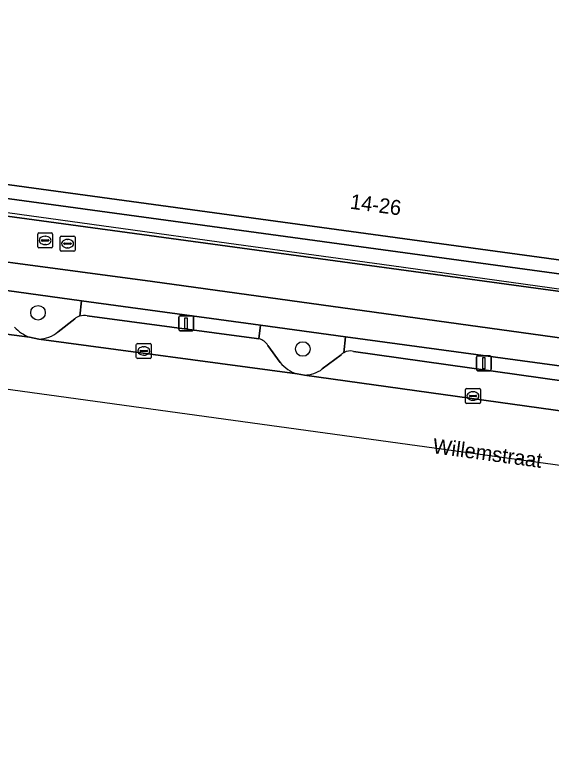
# Model space of a CAD drawing. Extents: x 160675 to 161153, y 383241 to 383714.
# Drawn here: x 160812.1 to 160848, y 383249.4 to 383299.9 of the extents above; entities that cross this region are included whole.
import ezdxf

# ---------------------------------------------------------------- set-up
doc = ezdxf.new("R2010")
doc.units = 0
for name, color, linetype in [('IMGEO_Berm_open', 7, 'Continuous'), ('IMGEO_Boom', 7, 'Continuous'), ('IMGEO_Fietspad_gesloten', 7, 'Continuous'), ('IMGEO_Groenvoorziening', 7, 'Continuous'), ('IMGEO_Kolk', 7, 'Continuous'), ('IMGEO_Lichtmast', 7, 'Continuous'), ('IMGEO_Lijnafwatering', 7, 'Continuous'), ('IMGEO_Openbare_ruimte_label', 7, 'Continuous'), ('IMGEO_Pand', 7, 'Continuous'), ('IMGEO_Pand_nummerreeks', 7, 'Continuous'), ('IMGEO_Parkeervlak_open', 7, 'Continuous'), ('IMGEO_Rijbaan_lokaal_gesloten', 7, 'Continuous'), ('IMGEO_Rioolput', 7, 'Continuous'), ('IMGEO_Voetpad_open', 7, 'Continuous')]:
    doc.layers.add(name, color=color, linetype=linetype)

msp = doc.modelspace()

# ---------------------------------------------------------------- linework, layer by layer
at = {"layer": 'IMGEO_Berm_open'}
for points in [[(160816.508, 383280.767), (160816.39, 383279.735)], [(160816.898, 383279.766), (160828.237, 383278.23), (160828.392, 383278.214), (160828.488, 383279.134), (160816.508, 383280.767)], [(160834.185, 383278.357), (160834.067, 383277.286)], [(160834.72, 383277.375), (160851.999, 383274.936), (160852.13, 383275.911), (160834.185, 383278.357)]]:
    msp.add_lwpolyline(points, dxfattribs=at)
for centre, radius, start, end in [((160816.705, 383278.753), 1.031, 79.202, 107.7821), ((160834.498, 383276.565), 0.84, 74.6568, 120.8657)]:
    msp.add_arc(centre, radius, start, end, dxfattribs=at)
at = {"layer": 'IMGEO_Boom'}
for centre in [(160813.6, 383279.958), (160831.33, 383277.536)]:
    msp.add_circle(centre, 0.489, dxfattribs=at)
at = {"layer": 'IMGEO_Fietspad_gesloten'}
for points in [[(160739.615, 383290.854), (160758.605, 383288.201), (160769.706, 383286.77), (160771.45, 383286.574), (160777.852, 383285.853), (160783.082, 383285.264), (160794.632, 383283.749), (160799.634, 383283.067), (160810.848, 383281.538), (160816.508, 383280.767), (160828.488, 383279.134), (160834.185, 383278.357), (160852.13, 383275.911), (160857.577, 383275.169), (160873.203, 383273.039)], [(161055.654, 383249.406), (161021.974, 383254.146), (161015.584, 383255.032), (160917.876, 383268.672), (160905.957, 383270.323), (160821.26, 383282.051), (160802.2, 383284.6)]]:
    msp.add_lwpolyline(points, dxfattribs=at)
at = {"layer": 'IMGEO_Groenvoorziening'}
for points in [[(160816.508, 383280.767), (160810.848, 383281.538), (160810.747, 383280.513)], [(160816.39, 383279.735), (160816.508, 383280.767)], [(160814.939, 383278.675), (160816.068, 383279.564)], [(160834.185, 383278.357), (160828.488, 383279.134), (160828.392, 383278.214)], [(160813.035, 383278.32), (160813.66, 383278.199)], [(160834.067, 383277.286), (160834.185, 383278.357)], [(160828.998, 383277.777), (160829.819, 383276.632)], [(160832.635, 383276.197), (160833.888, 383277.144)], [(160830.95, 383275.871), (160831.433, 383275.789)]]:
    msp.add_lwpolyline(points, dxfattribs=at)
for centre, radius, start, end in [((160816.696, 383278.771), 1.012, 107.5905, 128.3511), ((160813.858, 383280.597), 2.421, 221.0527, 250.1293), ((160813.548, 383280.455), 2.259, 272.8332, 307.9939), ((160828.223, 383277.341), 0.889, 29.3593, 79.0483), ((160834.516, 383276.536), 0.874, 120.9154, 135.9343), ((160831.571, 383278.014), 2.232, 218.2804, 253.8499), ((160831.444, 383277.732), 1.943, 269.6857, 307.8122)]:
    msp.add_arc(centre, radius, start, end, dxfattribs=at)
at = {"layer": 'IMGEO_Kolk'}
for p, q in [((160820.183, 383276.976), (160820.183, 383277.828)), ((160820.258, 383277.902), (160821.11, 383277.902)), ((160821.184, 383277.828), (160821.184, 383276.976)), ((160820.442, 383277.396), (160820.442, 383277.408)), ((160820.88, 383277.359), (160820.482, 383277.359)), ((160820.485, 383277.445), (160820.883, 383277.445)), ((160820.671, 383277.682), (160820.696, 383277.682)), ((160820.926, 383277.408), (160820.926, 383277.396)), ((160821.11, 383276.902), (160820.258, 383276.902)), ((160820.694, 383277.122), (160820.669, 383277.122)), ((160842.22, 383273.96), (160842.22, 383274.812)), ((160842.295, 383274.886), (160843.147, 383274.886)), ((160843.221, 383274.812), (160843.221, 383273.96)), ((160842.479, 383274.38), (160842.479, 383274.392)), ((160842.917, 383274.343), (160842.519, 383274.343)), ((160842.522, 383274.429), (160842.92, 383274.429)), ((160842.708, 383274.666), (160842.733, 383274.666)), ((160842.963, 383274.392), (160842.963, 383274.38)), ((160843.147, 383273.886), (160842.295, 383273.886)), ((160842.731, 383274.106), (160842.706, 383274.106))]:
    msp.add_line(p, q, dxfattribs=at)
for points in [[(160820.183, 383276.976), (160820.183, 383277.828)], [(160820.258, 383277.902), (160821.11, 383277.902)], [(160821.184, 383277.828), (160821.184, 383276.976)], [(160821.11, 383276.902), (160820.258, 383276.902)], [(160842.22, 383273.96), (160842.22, 383274.812)], [(160842.295, 383274.886), (160843.147, 383274.886)], [(160843.221, 383274.812), (160843.221, 383273.96)], [(160843.147, 383273.886), (160842.295, 383273.886)]]:
    msp.add_lwpolyline(points, dxfattribs=at)
for centre, radius, start, end in [((160820.26, 383277.826), 0.0765, 91.552, 178.448), ((160820.26, 383277.826), 0.0765, 91.552, 178.448), ((160821.108, 383277.826), 0.0765, 1.552, 88.448), ((160821.108, 383277.826), 0.0765, 1.552, 88.448), ((160820.482, 383277.405), 0.0403, 85.8775, 175.7526), ((160820.479, 383277.395), 0.0366, 178.938, 274.7102), ((160820.883, 383277.402), 0.043, 264.8664, 352.4533), ((160820.887, 383277.407), 0.0386, 1.7309, 96.639), ((160820.26, 383276.978), 0.0765, 181.552, 268.448), ((160820.26, 383276.978), 0.0765, 181.552, 268.448), ((160821.108, 383276.978), 0.0765, 271.552, 358.448), ((160821.108, 383276.978), 0.0765, 271.552, 358.448), ((160842.297, 383274.81), 0.0765, 91.552, 178.448), ((160842.297, 383274.81), 0.0765, 91.552, 178.448), ((160843.145, 383274.81), 0.0765, 1.552, 88.448), ((160843.145, 383274.81), 0.0765, 1.552, 88.448), ((160842.519, 383274.389), 0.0403, 85.8775, 175.7526), ((160842.516, 383274.379), 0.0366, 178.938, 274.7102), ((160842.92, 383274.386), 0.043, 264.8664, 352.4533), ((160842.924, 383274.391), 0.0386, 1.7309, 96.639), ((160842.297, 383273.962), 0.0765, 181.552, 268.448), ((160842.297, 383273.962), 0.0765, 181.552, 268.448), ((160843.145, 383273.962), 0.0765, 271.552, 358.448), ((160843.145, 383273.962), 0.0765, 271.552, 358.448)]:
    msp.add_arc(centre, radius, start, end, dxfattribs=at)
for centre, major_axis, ratio, start_param, end_param in [((160820.67, 383277.402), (-0.387, 0.002), 0.722429, 4.712389, 7.853982), ((160820.695, 383277.402), (-0.39, 0.002), 0.717154, 1.570796, 4.712389), ((160842.707, 383274.386), (-0.387, 0.002), 0.722429, 4.712389, 7.853982), ((160842.732, 383274.386), (-0.39, 0.002), 0.717154, 1.570796, 4.712389)]:
    msp.add_ellipse(centre, major_axis=major_axis, ratio=ratio, start_param=start_param, end_param=end_param, dxfattribs=at)
at = {"layer": 'IMGEO_Lichtmast'}
for p, q in [((160823.02, 383278.857), (160823.02, 383279.657)), ((160823.02, 383279.657), (160823.02, 383278.857)), ((160823.12, 383279.757), (160823.91, 383279.757)), ((160823.91, 383279.757), (160823.12, 383279.757)), ((160824.01, 383279.657), (160824.01, 383278.857)), ((160824.01, 383278.857), (160824.01, 383279.657)), ((160823.91, 383278.757), (160823.12, 383278.757)), ((160823.12, 383278.757), (160823.91, 383278.757)), ((160842.953, 383276.179), (160842.953, 383276.979)), ((160842.953, 383276.979), (160842.953, 383276.179)), ((160843.053, 383277.079), (160843.843, 383277.079)), ((160843.843, 383277.079), (160843.053, 383277.079)), ((160843.943, 383276.979), (160843.943, 383276.179)), ((160843.943, 383276.179), (160843.943, 383276.979)), ((160843.843, 383276.079), (160843.053, 383276.079)), ((160843.053, 383276.079), (160843.843, 383276.079))]:
    msp.add_line(p, q, dxfattribs=at)
for points in [[(160823.44, 383279.632), (160823.59, 383279.632), (160823.59, 383278.882), (160823.44, 383278.882), (160823.44, 383279.632)], [(160843.373, 383276.954), (160843.523, 383276.954), (160843.523, 383276.204), (160843.373, 383276.204), (160843.373, 383276.954)]]:
    msp.add_lwpolyline(points, dxfattribs=at)
for centre, start, end in [((160823.12, 383279.657), 90, 180), ((160823.12, 383279.657), 90, 180), ((160823.91, 383279.657), 0, 90), ((160823.91, 383279.657), 360, 90), ((160823.12, 383278.857), 180, 270), ((160823.12, 383278.857), 180, 270), ((160823.91, 383278.857), 270, 0), ((160823.91, 383278.857), 270, 0), ((160843.053, 383276.979), 90, 180), ((160843.053, 383276.979), 90, 180), ((160843.843, 383276.979), 0, 90), ((160843.843, 383276.979), 360, 90), ((160843.053, 383276.179), 180, 270), ((160843.053, 383276.179), 180, 270), ((160843.843, 383276.179), 270, 0), ((160843.843, 383276.179), 270, 0)]:
    msp.add_arc(centre, 0.1, start, end, dxfattribs=at)
at = {"layer": 'IMGEO_Lijnafwatering'}
for points in [[(160825.728, 383284.689), (160819.957, 383285.485), (160802.645, 383287.876)], [(160848.81, 383281.501), (160837.269, 383283.095), (160825.728, 383284.689)]]:
    msp.add_lwpolyline(points, dxfattribs=at)
at = {"layer": 'IMGEO_Pand'}
msp.add_lwpolyline([(160810.196, 383288.729), (160850.265, 383283.27), (160863.734, 383281.435), (160876.566, 383279.687), (160877.358, 383282.151), (160883.064, 383299.902)], dxfattribs=at)
at = {"layer": 'IMGEO_Parkeervlak_open'}
for points in [[(160800.901, 383279.923), (160813.035, 383278.32)], [(160816.068, 383279.564), (160814.939, 383278.675)], [(160828.392, 383278.214), (160828.237, 383278.23), (160816.898, 383279.766)], [(160813.66, 383278.199), (160830.95, 383275.871)], [(160829.819, 383276.632), (160828.998, 383277.777)], [(160851.999, 383274.936), (160834.72, 383277.375)], [(160833.888, 383277.144), (160832.635, 383276.197)], [(160831.433, 383275.789), (160854.652, 383272.548)]]:
    msp.add_lwpolyline(points, dxfattribs=at)
for centre, radius, start, end in [((160816.696, 383278.771), 1.012, 107.5905, 128.3511), ((160816.705, 383278.753), 1.031, 79.202, 107.7821), ((160813.858, 383280.597), 2.421, 221.0527, 250.1293), ((160813.548, 383280.455), 2.259, 272.8332, 307.9939), ((160828.223, 383277.341), 0.889, 29.3593, 79.0483), ((160834.516, 383276.536), 0.874, 120.9154, 135.9343), ((160834.498, 383276.565), 0.84, 74.6568, 120.8657), ((160831.571, 383278.014), 2.232, 218.2804, 253.8499), ((160831.444, 383277.732), 1.943, 269.6857, 307.8122)]:
    msp.add_arc(centre, radius, start, end, dxfattribs=at)
at = {"layer": 'IMGEO_Rijbaan_lokaal_gesloten'}
for points in [[(160769.912, 383285.718), (160720.857, 383292.423), (160716.095, 383293.073), (160715.848, 383293.119), (160712.137, 383293.632), (160711.352, 383293.738), (160711.332, 383290.596), (160711.318, 383288.264), (160749.307, 383283.418), (160760.039, 383281.939), (160789.689, 383277.854), (160896.852, 383263.09)], [(160896.852, 383263.09), (160897.357, 383266.625), (160878.574, 383269.26), (160875.826, 383269.639), (160875.72, 383269.65), (160872.814, 383270.055), (160872.393, 383270.131), (160855.077, 383272.545), (160854.652, 383272.548), (160831.433, 383275.789), (160830.95, 383275.871), (160813.66, 383278.199), (160813.035, 383278.32), (160800.901, 383279.923), (160799.302, 383280.124), (160799.145, 383280.144), (160778.824, 383282.894), (160778.227, 383282.961), (160777.552, 383283.158), (160777.187, 383283.264), (160771.71, 383285.271), (160771.308, 383285.419)]]:
    msp.add_lwpolyline(points, dxfattribs=at)
at = {"layer": 'IMGEO_Rioolput'}
for p, q in [((160813.58, 383284.383), (160813.58, 383285.235)), ((160813.655, 383285.309), (160814.507, 383285.309)), ((160813.882, 383284.852), (160814.28, 383284.852)), ((160814.068, 383285.089), (160814.093, 383285.089)), ((160814.581, 383285.235), (160814.581, 383284.383)), ((160815.079, 383284.163), (160815.079, 383285.015)), ((160815.154, 383285.089), (160816.006, 383285.089)), ((160815.567, 383284.869), (160815.592, 383284.869)), ((160816.08, 383285.015), (160816.08, 383284.163)), ((160813.839, 383284.803), (160813.839, 383284.815)), ((160814.277, 383284.766), (160813.879, 383284.766)), ((160814.091, 383284.529), (160814.066, 383284.529)), ((160814.323, 383284.815), (160814.323, 383284.803)), ((160815.338, 383284.583), (160815.338, 383284.595)), ((160815.776, 383284.546), (160815.378, 383284.546)), ((160815.381, 383284.632), (160815.779, 383284.632)), ((160815.822, 383284.595), (160815.822, 383284.583)), ((160814.507, 383284.309), (160813.655, 383284.309)), ((160816.006, 383284.089), (160815.154, 383284.089)), ((160815.59, 383284.309), (160815.565, 383284.309))]:
    msp.add_line(p, q, dxfattribs=at)
for points in [[(160813.58, 383284.383), (160813.58, 383285.235)], [(160813.655, 383285.309), (160814.507, 383285.309)], [(160814.581, 383285.235), (160814.581, 383284.383)], [(160815.079, 383284.163), (160815.079, 383285.015)], [(160815.154, 383285.089), (160816.006, 383285.089)], [(160816.08, 383285.015), (160816.08, 383284.163)], [(160814.507, 383284.309), (160813.655, 383284.309)], [(160816.006, 383284.089), (160815.154, 383284.089)]]:
    msp.add_lwpolyline(points, dxfattribs=at)
for centre, radius, start, end in [((160813.657, 383285.233), 0.0765, 91.552, 178.448), ((160813.657, 383285.233), 0.0765, 91.552, 178.448), ((160813.879, 383284.812), 0.0403, 85.8775, 175.7526), ((160814.284, 383284.814), 0.0386, 1.7309, 96.639), ((160814.505, 383285.233), 0.0765, 1.552, 88.448), ((160814.505, 383285.233), 0.0765, 1.552, 88.448), ((160815.156, 383285.013), 0.0765, 91.552, 178.448), ((160815.156, 383285.013), 0.0765, 91.552, 178.448), ((160816.004, 383285.013), 0.0765, 1.552, 88.448), ((160816.004, 383285.013), 0.0765, 1.552, 88.448), ((160813.657, 383284.385), 0.0765, 181.552, 268.448), ((160813.657, 383284.385), 0.0765, 181.552, 268.448), ((160813.876, 383284.802), 0.0366, 178.938, 274.7102), ((160814.28, 383284.809), 0.043, 264.8664, 352.4533), ((160814.505, 383284.385), 0.0765, 271.552, 358.448), ((160814.505, 383284.385), 0.0765, 271.552, 358.448), ((160815.378, 383284.592), 0.0403, 85.8775, 175.7526), ((160815.375, 383284.582), 0.0366, 178.938, 274.7102), ((160815.779, 383284.589), 0.043, 264.8664, 352.4533), ((160815.783, 383284.594), 0.0386, 1.7309, 96.639), ((160815.156, 383284.165), 0.0765, 181.552, 268.448), ((160815.156, 383284.165), 0.0765, 181.552, 268.448), ((160816.004, 383284.165), 0.0765, 271.552, 358.448), ((160816.004, 383284.165), 0.0765, 271.552, 358.448)]:
    msp.add_arc(centre, radius, start, end, dxfattribs=at)
for centre, major_axis, ratio, start_param, end_param in [((160814.067, 383284.809), (-0.387, 0.002), 0.722429, 4.712389, 7.853982), ((160814.092, 383284.809), (-0.39, 0.002), 0.717154, 1.570796, 4.712389), ((160815.566, 383284.589), (-0.387, 0.002), 0.722429, 4.712389, 7.853982), ((160815.591, 383284.589), (-0.39, 0.002), 0.717154, 1.570796, 4.712389)]:
    msp.add_ellipse(centre, major_axis=major_axis, ratio=ratio, start_param=start_param, end_param=end_param, dxfattribs=at)
at = {"layer": 'IMGEO_Voetpad_open'}
for points in [[(160796.624, 383289.648), (160796.9, 383290.54), (160796.79, 383290.554), (160794.963, 383290.783), (160793.033, 383291.064), (160792.786, 383289.105), (160802.815, 383287.733), (160802.783, 383287.634), (160809.546, 383286.711), (160856.427, 383280.313), (160863.161, 383279.396), (160876.234, 383277.589), (160877.665, 383282.1), (160877.358, 383282.151), (160876.566, 383279.687), (160876.281, 383278.779)], [(160796.9, 383290.54), (160796.624, 383289.648), (160876.281, 383278.779), (160876.566, 383279.687), (160863.734, 383281.435), (160850.265, 383283.27), (160810.196, 383288.729)]]:
    msp.add_lwpolyline(points, close=True, dxfattribs=at)
for points in [[(160905.752, 383272.875), (160904.857, 383273.04), (160904.953, 383273.337), (160894.651, 383274.74), (160878.327, 383277.067), (160876.161, 383277.392), (160876.234, 383277.589), (160863.161, 383279.396), (160862.981, 383278.755), (160856.362, 383279.656), (160856.246, 383279.668), (160856.427, 383280.313), (160809.546, 383286.711), (160809.336, 383286.059), (160802.573, 383286.982), (160802.783, 383287.634), (160802.815, 383287.733), (160792.786, 383289.105), (160792.609, 383287.837)], [(160794.456, 383285.635), (160802.2, 383284.6), (160821.26, 383282.051), (160905.957, 383270.323), (160917.876, 383268.672), (161015.584, 383255.032)]]:
    msp.add_lwpolyline(points, dxfattribs=at)

# ---------------------------------------------------------------- texts
at = {"layer": 'IMGEO_Openbare_ruimte_label'}
msp.add_text('Willemstraat', height=1, rotation=352.1858, dxfattribs=at).set_placement((160839.979, 383270.565))
at = {"layer": 'IMGEO_Pand_nummerreeks'}
msp.add_text('14-26', height=1, rotation=352.2422, dxfattribs=at).set_placement((160834.455, 383286.938))

doc.saveas('drawing.dxf')
